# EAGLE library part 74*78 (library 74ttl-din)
Dual J-K FLIP FLOP, preset, common clock and common clear
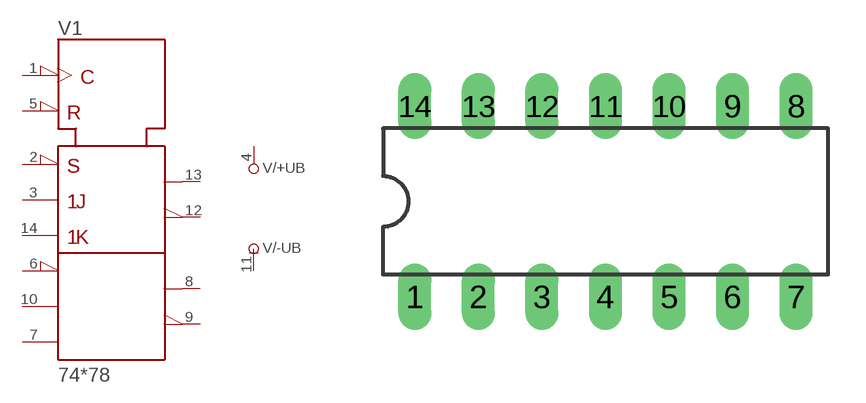
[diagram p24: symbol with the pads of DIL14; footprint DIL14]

Designator prefix V; gates /+UB=+UB /-UB=-UB 1=78

## 7478N  [DIL14]
1  1:CLK  in
2  1:1PRE\  in
3  1:1J  in
4  /+UB:+UB  pwr
5  1:CLR\  in
6  1:2PRE\  in
7  1:2K  in
8  1:2Q  out
9  1:2Q\  out
10  1:2J  in
11  /-UB:-UB  pwr
12  1:1Q\  out
13  1:1Q  out
14  1:1K  in

## Footprint DIL14 (pad centres in mm)
Dual In Line Package
drill 0.813 long: 1 -7.62,-3.81; 2 -5.08,-3.81; 3 -2.54,-3.81; 4 0,-3.81; 5 2.54,-3.81; 6 5.08,-3.81; 7 7.62,-3.81; 8 7.62,3.81; 9 5.08,3.81; 10 2.54,3.81; 11 0,3.81; 12 -2.54,3.81; 13 -5.08,3.81; 14 -7.62,3.81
